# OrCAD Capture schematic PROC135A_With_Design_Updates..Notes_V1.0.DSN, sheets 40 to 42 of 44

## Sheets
40 40. HDMI INTERFACE: size C; title: HDMI INTERFACE
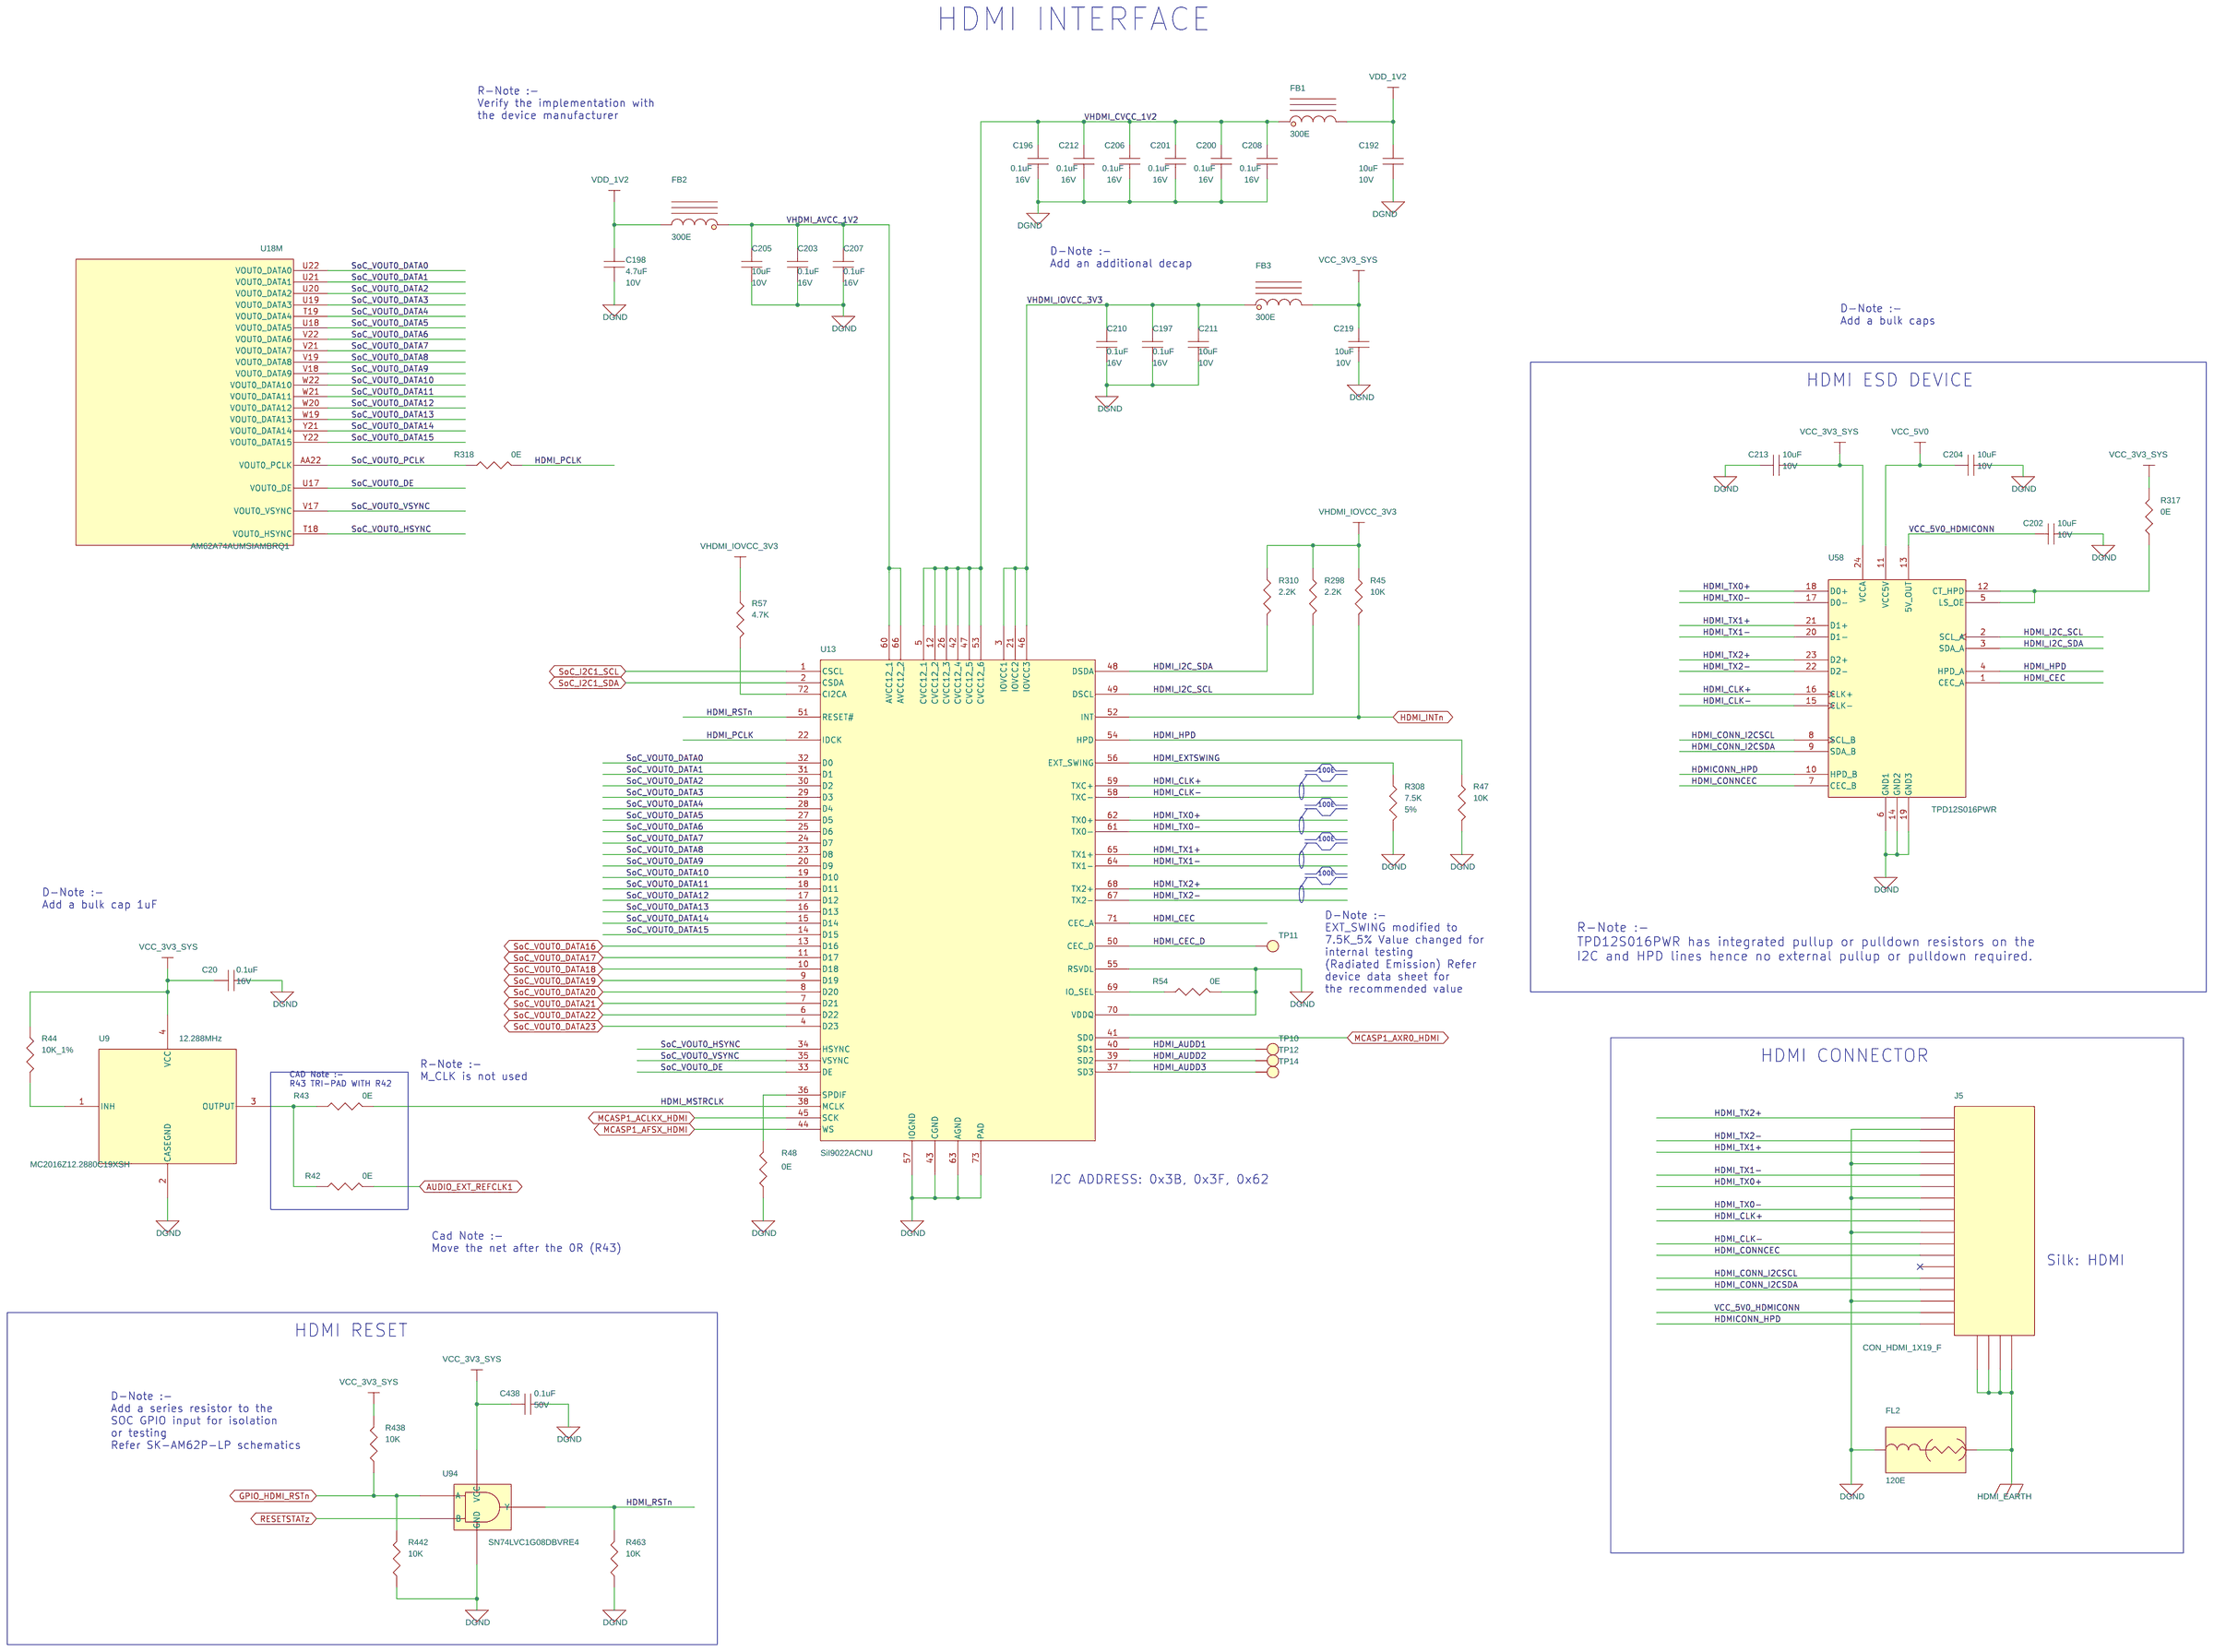
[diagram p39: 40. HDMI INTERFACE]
41 41. OSCILLATOR: size C; title: OSCILLATOR
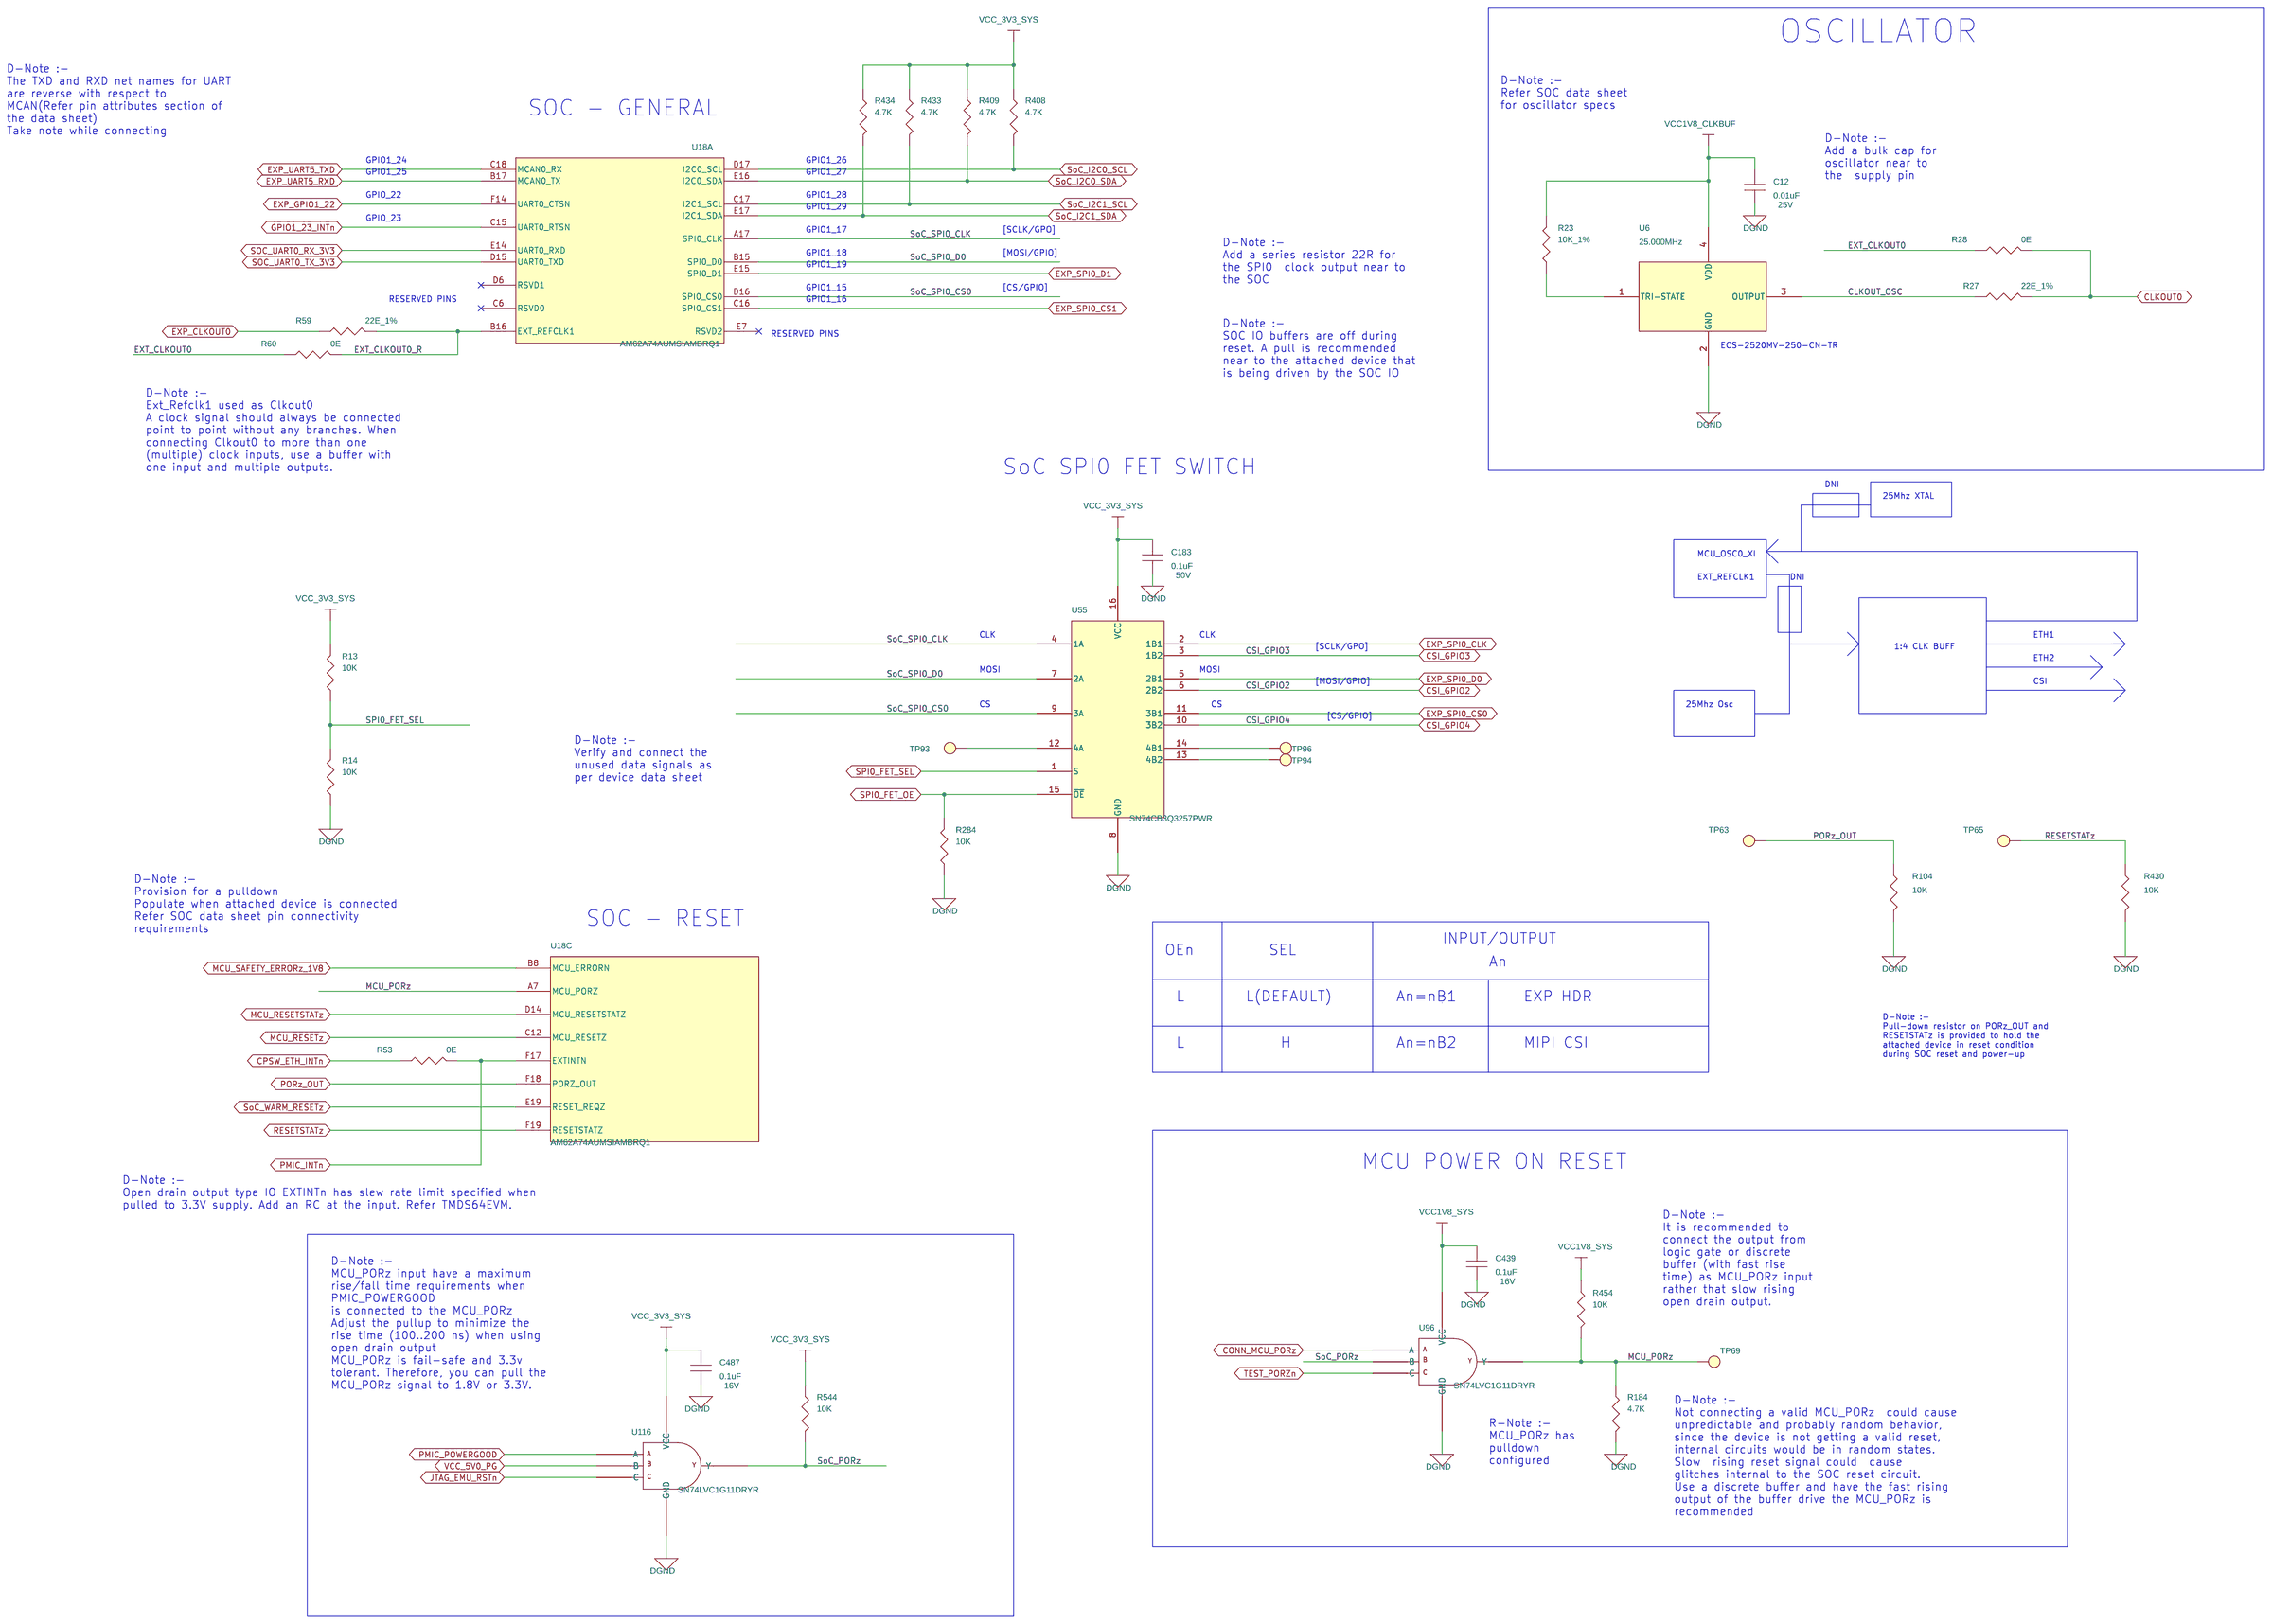
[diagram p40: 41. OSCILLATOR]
42 42. RESET: size C; title: RESET
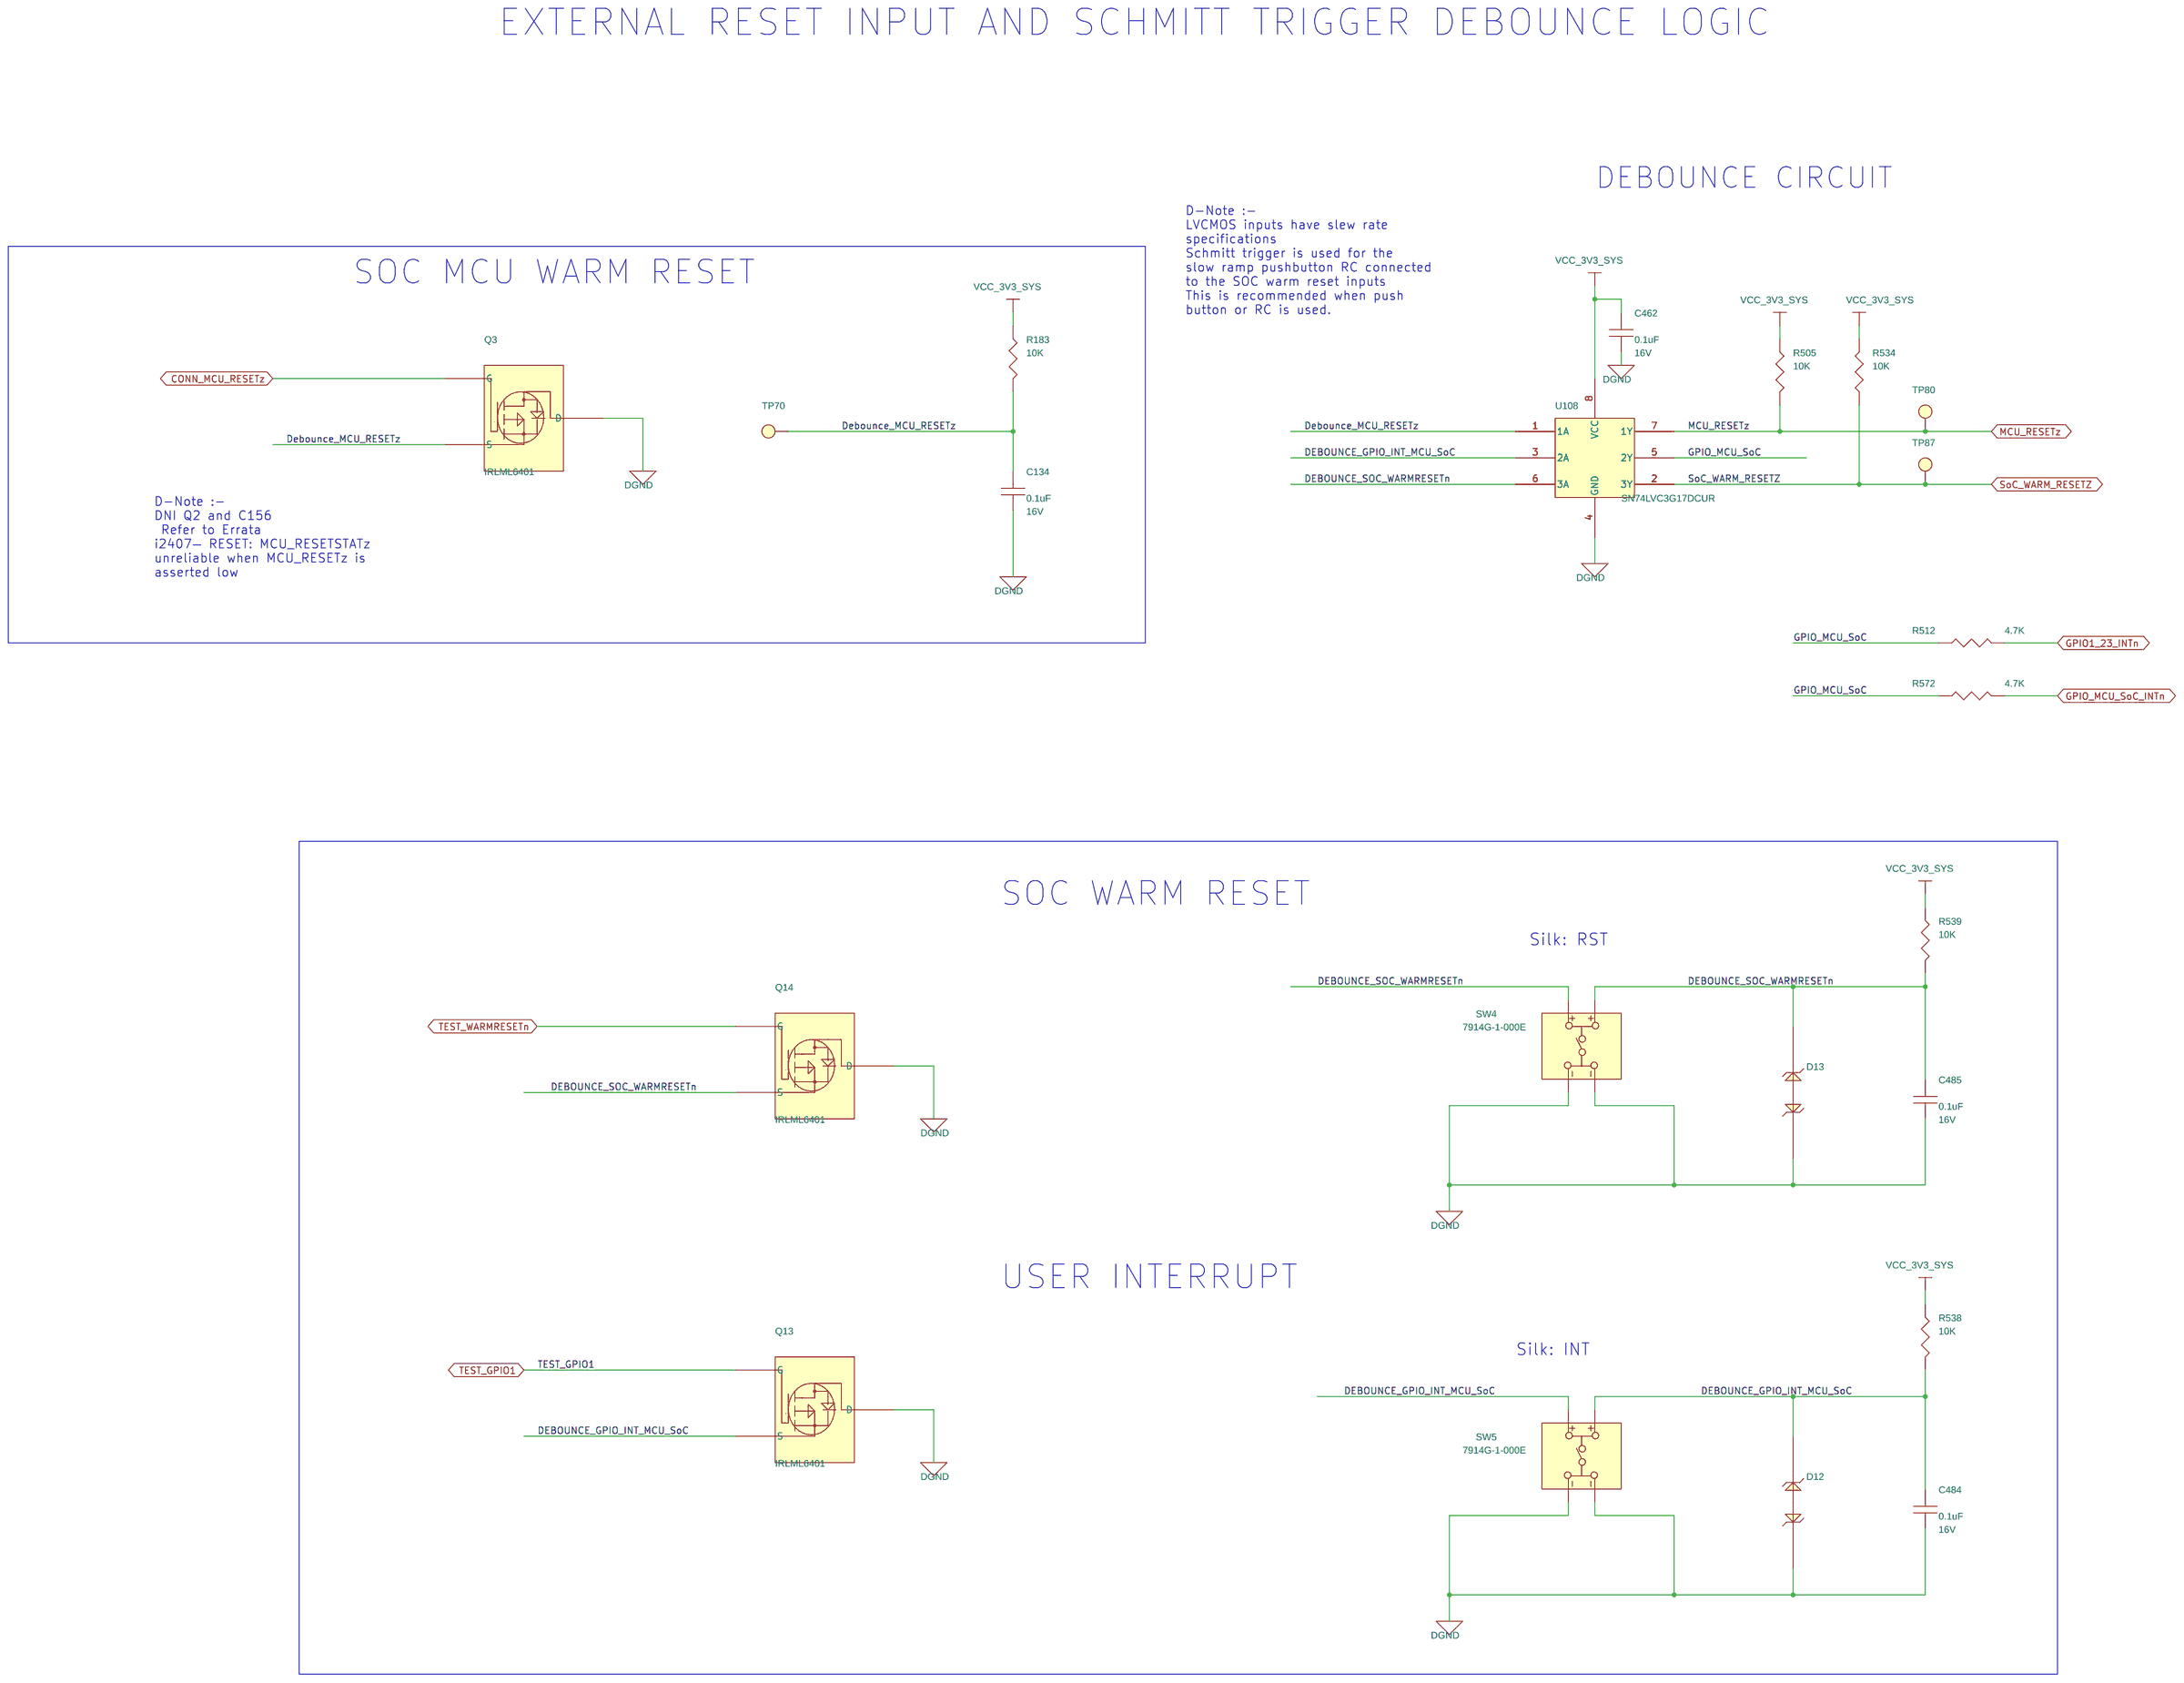
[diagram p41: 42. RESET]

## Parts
sheet 40. HDMI INTERFACE
C20  0.1uF  [CAP0201_0-5]
C192  10uF  [CAP0402_0-75]
C196  0.1uF  [CAP0201_0-5]
C197  0.1uF  [CAP0201_0-5]
C198  4.7uF  [CAP0402_0-75]
C200  0.1uF  [CAP0201_0-5]
C201  0.1uF  [CAP0201_0-5]
C202  10uF  [CAP0402_0-75]
C203  0.1uF  [CAP0201_0-5]
C204  10uF  [CAP0402_0-75]
C205  10uF  [CAP0402_0-75]
C206  0.1uF  [CAP0201_0-5]
C207  0.1uF  [CAP0201_0-5]
C208  0.1uF  [CAP0201_0-5]
C210  0.1uF  [CAP0201_0-5]
C211  10uF  [CAP0402_0-75]
C212  0.1uF  [CAP0201_0-5]
C213  10uF  [CAP0402_0-75]
C219  10uF  [CAP0402_0-75]
C438  0.1uF  [CAP0402_0-75]
FB1  300E  [IND0603]
FB2  300E  [IND0603]
FB3  300E  [IND0603]
FL2  120E  [EMIFIL_BLM15A_0402_0-6]
J5  CON_HDMI_1X19_F  [CON_19X1_10029449-001RLF_S_R_S_6-3]
R42  0E  [RES0201_0-5]
R43  0E  [RES0201_0-5]
R44  10K_1%  [RES0201_0-5]
R45  10K  [RES0201_0-5]
R47  10K  [RES0201_0-5]
R48  0E  [RES0201_0-5]
R54  0E  [RES0201_0-5]
R57  4.7K  [RES0201_0-5]
R298  2.2K  [RES0402_0-5]
R308  7.5K  [RES0402_0-5]
R310  2.2K  [RES0402_0-5]
R317  0E  [RES0201_0-5]
R318  0E  [RES0201_0-5]
R438  10K  [RES0201_0-5]
R442  10K  [RES0201_0-5]
R463  10K  [RES0201_0-5]
TP10  TP20_SMD  [TP20_SMD]
TP11  TP20_SMD  [TP20_SMD]
TP12  TP20_SMD  [TP20_SMD]
TP14  TP20_SMD  [TP20_SMD]
U9  12.288MHz  [OSC4_KC2016K_80X60_SMD_0-8]
U13  SiI9022ACNU  [QFN72_19-68_390X390_0-9]
U58  TPD12S016PWR  [TSSOP24_25-59_315X180_1-2]
U94  SN74LVC1G08DBVRE4  [SOT23-5]
sheet 41. OSCILLATOR
C12  0.01uF  [CAP0201_0-5]
C183  0.1uF  [CAP0402_0-75]
C439  0.1uF  [CAP0201_0-5]
C487  0.1uF  [CAP0201_0-5]
R13  10K  [RES0201_0-5]
R14  10K  [RES0201_0-5]
R23  10K_1%  [RES0201_0-5]
R27  22E_1%  [RES0201_0-5]
R28  0E  [RES0201_0-5]
R53  0E  [RES0201_0-5]
R59  22E_1%  [RES0201_0-5]
R60  0E  [RES0201_0-5]
R104  10K  [RES0201_0-5]
R184  4.7K  [RES0201_0-5]
R284  10K  [RES0201_0-5]
R408  4.7K  [RES0201_0-5]
R409  4.7K  [RES0201_0-5]
R430  10K  [RES0201_0-5]
R433  4.7K  [RES0201_0-5]
R434  4.7K  [RES0201_0-5]
R454  10K  [RES0201_0-5]
R544  10K  [RES0201_0-5]
TP63  TP20_SMD  [TP20_SMD]
TP65  TP20_SMD  [TP20_SMD]
TP69  TP20_SMD  [TP20_SMD]
TP93  TP20_SMD  [TP20_SMD]
TP94  TP20_SMD  [TP20_SMD]
TP96  TP20_SMD  [TP20_SMD]
U6  25.000MHz  [OSC4_ECS-2520MV_100X80_SMD_0-9]
U18  AM62A74AUMSIAMBRQ1  [FBGA484_31-49_710X710_2-7]  (sections A,B,C,D,E,F,G,H,I,J,K,L,M,N,O,P,Q)
U55  SN74CB3Q3257PWR  [TSSOP16_25-59_205X180]
U96  SN74LVC1G11DRYR  [SON6_SN74LVC2G17_40X60_0-6]
U116  SN74LVC1G11DRYR  [SON6_SN74LVC2G17_40X60_0-6]
sheet 42. RESET
C134  0.1uF  [CAP0201_0-5]
C462  0.1uF  [CAP0201_0-5]
C484  0.1uF  [CAP0201_0-5]
C485  0.1uF  [CAP0201_0-5]
D12  TPD1E10B06DPYR  [DIO_DFN0402_0-5]
D13  TPD1E10B06DPYR  [DIO_DFN0402_0-5]
Q3  IRLML6401  [TO_SOT23-123]
Q13  IRLML6401  [TO_SOT23-123]
Q14  IRLML6401  [TO_SOT23-123]
R183  10K  [RES0201_0-5]
R505  10K  [RES0201_0-5]
R512  4.7K  [RES0201_0-5]
R534  10K  [RES0201_0-5]
R538  10K  [RES0201_0-5]
R539  10K  [RES0201_0-5]
R572  4.7K  [RES0201_0-5]
SW4  7914G-1-000E  [SW4_100X216_200X200_SMD_4-2]
SW5  7914G-1-000E  [SW4_100X216_200X200_SMD_4-2]
TP70  TP20_SMD  [TP20_SMD]
TP80  TP20_SMD  [TP20_SMD]
TP87  TP20_SMD  [TP20_SMD]
U108  SN74LVC3G17DCUR  [VSSOP8_19-68_85X95_0-9]

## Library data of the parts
C20 C134 C439 C462 C484 C485 C487 = CAP: CAP CERAMIC 0.1uF 16V 10% X5R 0201; Alt_Mfr_name: YAGEO AMERICA; Alt_Mfr_part_number: CC0402KRX5R8BB104; Chkd/date: MANIRAJA/230118; Crtd /date: MANIRAJA/230118; Custom_Duty: 15%; Customs_HS_Code: 85322990; Distributor_name: DIGIKEY; Distributor_part_number: 490-14305-1-ND; Footprint Path: Y:\MIS_DATABASE\Library\ALTIUM_TOOL\PCB_FOOTPRINTS\Altium_Footprint_Lib.PcbLib; Height: 0.33MM; Library Path: Y:\MIS_DATABASE\Library\ALTIUM_TOOL\SCHEMATICS_PARTS\MS_DISCRETE_Library.schlib; Mfr_name: MURATA; Mfr_part_number: GRM033R61C104KE14D; Mistral Part No: 120009030072-R; Package: 0201; Part_type: CAPACITORS\CERAMIC; Project: TI_MAXIE_CPB; RoHS: RoHS; Temperature: -55°C+85°C; Tolerance: 10%; Voltage: 16V; Wattage: NA; Weight: 0.33mg; Datasheet: Y:\MIS_DATABASE\DATASHEETS\CAPACITORS\GRM033R61C104KE14.PDF
C192 C202 C204 C205 C211 C213 C219 = CAP: CAP CERAMIC 10uF 10V 20% X5R 0402; Chkd/date: MANIRAJA/300520; Crtd /date: ALVY/260520; Custom_Duty: 15%; Customs_HS_Code: 85322990; Distributor_name: DIGIKEY; Distributor_part_number: 490-GRM155R61A106ME11DTR-ND; Footprint Path: Y:\MIS_DATABASE\Library\ALTIUM_TOOL\PCB_FOOTPRINTS\Altium_Footprint_Lib.PcbLib; Height: 0.55MM; Library Path: Y:\MIS_DATABASE\Library\ALTIUM_TOOL\SCHEMATICS_PARTS\MS_DISCRETE_Library.schlib; Mfr_name: MURATA; Mfr_part_number: GRM155R61A106ME11D; Mistral Part No: 120013110019-R; Package: 0402; Part_type: CAPACITORS\CERAMIC; Project: QCS610_NANOSOM; RoHS: RoHS; Temperature: -55°C+85°C; Tolerance: 20%; Voltage: 10V; Wattage: NA; Weight: 3.1mg; Datasheet: Y:\MIS_DATABASE\DATASHEETS\CAPACITORS\MURATA-GXX-SER_NOV17.PDF
C196 C197 C200 C201 C203 C206-C208 C210 C212 = CAP: CAP CERAMIC 0.1uF 16V 10% X5R 0201; Chkd/date: MANIRAJA/230118; Crtd /date: MANIRAJA/230118; Custom_Duty: 15%; Customs_HS_Code: 85322990; Distributor_name: DIGIKEY; Distributor_part_number: 490-14305-1-ND; Footprint Path: Y:\MIS_DATABASE\Library\ALTIUM_TOOL\PCB_FOOTPRINTS\Altium_Footprint_Lib.PcbLib; Height: 0.33MM; Library Path: Y:\MIS_DATABASE\Library\ALTIUM_TOOL\SCHEMATICS_PARTS\MS_DISCRETE_Library.schlib; Mfr_name: MURATA; Mfr_part_number: GRM033R61C104KE14D; Mistral Part No: 120009030072-R; Package: 0201; Part_type: CAPACITORS\CERAMIC; Project: TI_MAXIE_CPB; RoHS: RoHS; Temperature: -55°C+85°C; Tolerance: 10%; Voltage: 16V; Wattage: NA; Weight: 0.33mg; Datasheet: Y:\MIS_DATABASE\DATASHEETS\CAPACITORS\GRM033R61C104KE14.PDF
C198 = CAP: CAP CERAMIC 4.7uF 10V 20% X5R 0402; Chkd/date: MANIRAJA/110718; Crtd /date: ALVY/110718; Custom_Duty: 15%; Customs_HS_Code: 85322990; Distributor_name: DIGIKEY; Distributor_part_number: 490-14306-1-ND; Footprint Path: Y:\MIS_DATABASE\Library\ALTIUM_TOOL\PCB_FOOTPRINTS\Altium_Footprint_Lib.PcbLib; Height: 0.65MM; Library Path: Y:\MIS_DATABASE\Library\ALTIUM_TOOL\SCHEMATICS_PARTS\MS_DISCRETE_Library.schlib; Mfr_name: MURATA; Mfr_part_number: GRM155R61A475MEAAD; Mistral Part No: 120012060002-R; Package: 0402; Part_type: CAPACITORS\CERAMIC; Project: TI_J7SVB_PCIE_ADD-ON-CARD; RoHS: RoHS; Temperature: -55°C+85°C; Tolerance: 20%; Voltage: 10V; Wattage: NA; Weight: 14mg; Datasheet: Y:\MIS_DATABASE\DATASHEETS\CAPACITORS\GRM155R61A475MEAAD.PDF
C183 C438 = CAP: CAP CERAMIC 0.1uF 50V 10% X7R 0402; Alt_Mfr_name: YAGEO AMERICA; Alt_Mfr_part_number: CC0402KRX5R8BB104; Chkd/date: MANIRAJA/261020; Crtd /date: ALVY/211020; Custom_Duty: 15%; Customs_HS_Code: 85322990; Distributor_name: DIGIKEY; Distributor_part_number: 490-10700-1-ND; Footprint Path: Y:\MIS_DATABASE\Library\ALTIUM_TOOL\PCB_FOOTPRINTS\Altium_Footprint_Lib.PcbLib; Height: 0.55MM; Library Path: Y:\MIS_DATABASE\Library\ALTIUM_TOOL\SCHEMATICS_PARTS\MS_DISCRETE_Library.schlib; Mfr_name: MURATA; Mfr_part_number: GRM155R71H104KE14D; Mistral Part No: 120011100014-R; Package: 0402; Part_type: CAPACITORS\CERAMIC; Project: J7_CP; RoHS: RoHS; Temperature: -55°C+125°C; Tolerance: 10%; Voltage: 50V; Wattage: NA; Weight: 3.1mg; Datasheet: Y:\MIS_DATABASE\DATASHEETS\CAPACITORS\GRM155R71H104KE14.PDF
FB1-FB3 = INDUCTOR_FERRITE: IND FERRITE CHIP 300E 500mA 0603; Alternate_mfr_name_A: TDK CORPORATION; Alternate_mfr_part_number_A: MMZ1608R301ATA00; Chkd/date: VASANTHA/190614; Crtd /date: NAVEED/160614; Custom_Duty: 24%; Customs_HS_Code: 85437099; Distributor_name: DIGIKEY; Distributor_name_A: DIGIKEY; Distributor_part_number: 445-2171-1-ND; Distributor_part_number_A: 445-2171-1-ND; Height: 0.75MM; Mfr_name: TDK CORPORATION; Mfr_part_number: MMZ1608R301A; Mistral Part No: 130014060028-R; Package: 0603; Part_type: INDUCTOR; Project: AEGIS_POM; RoHS: RoHS; Temperature: -55°C+125°C; Tolerance: NA; Voltage: NA; Wattage: NA; Weight: NA; Datasheet: Y:\MIS_DATABASE\DATASHEETS\DISCRETES\INDUCTORS\MMZSER.PDF
FL2 = EMIFILTER_IND: IND FERRITE BEAD CHIP 120E 2A 0402; Chkd/date: NAVEED/241114; Crtd /date: USMAN/170613; Custom_Duty: 24%; Customs_HS_Code: 85369090; Distributor_name: DIGIKEY; Distributor_part_number: 490-9656-1-ND; Footprint Path: Y:\MIS_DATABASE\Library\ALTIUM_TOOL\PCB_FOOTPRINTS\Altium_Footprint_Lib.PcbLib; Height: 0.55MM; Library Path: Y:\MIS_DATABASE\Library\ALTIUM_TOOL\SCHEMATICS_PARTS\MS_FILTER_Library.schlib; Mfr_name: MURATA; Mfr_part_number: BLM15PX121SN1D; Mistral Part No: 130013060022-R; Package: 0402; Part_type: INDUCTOR; Project: GEN_3-8; RoHS: RoHS; Temperature: -55°C+125°C; Tolerance: 25%; Voltage: NA; Wattage: NA; Weight: 1mg; Datasheet: Y:\MIS_DATABASE\DATASHEETS\DISCRETES\INDUCTORS\BLM15-SN1-SER.PDF
J5 = CON_HDMI_19X1: CON HDMI-A TYPE 1X19 0.50MM PITCH FEMALE RT SMD; Chkd/date: VASANTHA/060117; Crtd /date: MUDDU/060510; Custom_Duty: 24%; Customs_HS_Code: 85369090; Distributor_name: DIGIKEY; Distributor_part_number: 609-1010-1-ND; Footprint Path: Y:\MIS_DATABASE\Library\ALTIUM_TOOL\PCB_FOOTPRINTS\Altium_Footprint_Lib.PcbLib; Height: 6.30MM; Library Path: Y:\MIS_DATABASE\Library\ALTIUM_TOOL\SCHEMATICS_PARTS\MS_CONNECTOR_Library.schlib; Mfr_name: FCI; Mfr_part_number: 10029449-001RLF; Mistral Part No: 150010050001-R; Package: SMD; Part_type: CONNECTOR\HDMI; Project: SHIVA; RoHS: RoHS; Temperature: -20°C+85°C; Tolerance: NA; Voltage: NA; Wattage: NA; Weight: 2700mg; Datasheet: Y:\MIS_DATABASE\DATASHEETS\CONNECTORS\10029449-001RLF.PDF
R28 R42 R43 R48 R53 R54 R60 R317 = RESISTOR: RES 0E 1/20W 5% 0201; Chkd/date: NAVEED/301214; Crtd /date: MUDDU/120710; Custom_Duty: 15%; Customs_HS_Code: 85332119; Distributor_name: DIGIKEY; Distributor_part_number: 311-0.0NCT-ND; Footprint Path: Y:\MIS_DATABASE\Library\ALTIUM_TOOL\PCB_FOOTPRINTS\Altium_Footprint_Lib.PcbLib; Height: 0.26MM; Library Path: Y:\MIS_DATABASE\Library\ALTIUM_TOOL\SCHEMATICS_PARTS\MS_DISCRETE_Library.schlib; Mfr_name: YAGEO AMERICA; Mfr_part_number: RC0201JR-070RL; Mistral Part No: 110010070067-R; Package: 0201; Part_type: RESISTORS\FIXED; Project: PB_BUGBASE; RoHS: RoHS; Temperature: -55°C+125°C; Tolerance: 5%; Voltage: NA; Wattage: 1/20W; Weight: 0.17mg; Datasheet: Y:\MIS_DATABASE\DATASHEETS\RESISTORS\RCXXXXL-SER_MAR18.PDF
R23 R44 = RESISTOR: RES 10K 1/20W 1% 0201; Chkd/date: VASANTHA/270117; Crtd /date: MANIRAJA/270117; Custom_Duty: 15%; Customs_HS_Code: 85332119; Distributor_name: DIGIKEY; Distributor_part_number: 311-10.0KMCT-ND; Footprint Path: Y:\MIS_DATABASE\Library\ALTIUM_TOOL\PCB_FOOTPRINTS\Altium_Footprint_Lib.PcbLib; Height: 0.26MM; Library Path: Y:\MIS_DATABASE\Library\ALTIUM_TOOL\SCHEMATICS_PARTS\MS_DISCRETE_Library.schlib; Mfr_name: YAGEO AMERICA; Mfr_part_number: RC0201FR-0710KL; Mistral Part No: 110011040018-R; Package: 0201; Part_type: RESISTORS\FIXED; Project: GOLDEN-I LITE; RoHS: RoHS; Temperature: -55°C+125°C; Tolerance: 1%; Voltage: NA; Wattage: 1/20W; Weight: 0.17mg; Datasheet: Y:\MIS_DATABASE\DATASHEETS\RESISTORS\RCXXXXL-SER_MAR18.PDF
R13 R14 R45 R47 R104 R183 R284 R430 R438 R442 R454 R463 R505 R534 R538 R539 R544 = RESISTOR: RES 10K 1/20W 5% 0201; Chkd/date: MANIRAJA/050517; Crtd /date: MANIRAJA/050517; Custom_Duty: 15%; Customs_HS_Code: 85332119; Distributor_name: DIGIKEY; Distributor_part_number: 311-10KNCT-ND; Footprint Path: Y:\MIS_DATABASE\Library\ALTIUM_TOOL\PCB_FOOTPRINTS\Altium_Footprint_Lib.PcbLib; Height: 0.26MM; Library Path: Y:\MIS_DATABASE\Library\ALTIUM_TOOL\SCHEMATICS_PARTS\MS_DISCRETE_Library.schlib; Mfr_name: YAGEO AMERICA; Mfr_part_number: RC0201JR-0710KL; Mistral Part No: 110010070051-R; Package: 0201; Part_type: RESISTORS\FIXED; Project: GOLDEN-I LITE; RoHS: RoHS; Temperature: -55°C+125°C; Tolerance: 5%; Voltage: NA; Wattage: 1/20W; Weight: 0.17mg; Datasheet: Y:\MIS_DATABASE\DATASHEETS\RESISTORS\RCXXXXL-SER_MAR18.PDF
R57 R184 R408 R409 R433 R434 = RESISTOR: RES 4.7K 1/20W 5% 0201; Chkd/date: MANIRAJA/200921; Crtd /date: ALVY/200921; Custom_Duty: 15%; Customs_HS_Code: 85332119; Distributor_name: DIGIKEY; Distributor_part_number: 311-4.7KNCT-ND; Footprint Path: Y:\MIS_DATABASE\Library\ALTIUM_TOOL\PCB_FOOTPRINTS\Altium_Footprint_Lib.PcbLib; Height: 0.26MM; Library Path: Y:\MIS_DATABASE\Library\ALTIUM_TOOL\SCHEMATICS_PARTS\MS_DISCRETE_Library.schlib; Mfr_name: YAGEO AMERICA; Mfr_part_number: RC0201JR-074K7L; Mistral Part No: 110021090007-R; Package: 0201; Part_type: RESISTORS\FIXED; Project: TI_AM62x SKEVM_BRD; RoHS: RoHS; Temperature: -55°C+125°C; Tolerance: 5%; Voltage: NA; Wattage: 1/20W; Weight: 0.17mg; Datasheet: Y:\MIS_DATABASE\DATASHEETS\RESISTORS\RCXXXXL-SER_MAR18.PDF
R298 R310 = RESISTOR: RES 2.2K 1/16W 5% 0402; Chkd/date: VASANTHA/061216; Crtd /date: BAVISH/021210; Custom_Duty: 15%; Customs_HS_Code: 85332119; Distributor_name: DIGIKEY; Distributor_part_number: 311-2.2KJRCT-ND; Footprint Path: Y:\MIS_DATABASE\Library\ALTIUM_TOOL\PCB_FOOTPRINTS\Altium_Footprint_Lib.PcbLib; Height: 0.40MM; Library Path: Y:\MIS_DATABASE\Library\ALTIUM_TOOL\SCHEMATICS_PARTS\MS_DISCRETE_Library.schlib; Mfr_name: YAGEO AMERICA; Mfr_part_number: RC0402JR-072K2L; Mistral Part No: 110010120018-R; Package: 0402; Part_type: RESISTORS\FIXED; Project: TE4; RoHS: RoHS; Temperature: -55°C+155°C; Tolerance: 5%; Voltage: NA; Wattage: 1/16W; Weight: 0.65mg; Datasheet: Y:\MIS_DATABASE\DATASHEETS\RESISTORS\RCXXXXL-SER_MAR18.PDF
R308 = RESISTOR: RES 7.5K 1/16W 5% 0402; Chkd/date: MAZHAR/280108; Crtd /date: USMAN/280108; Custom_Duty: 15%; Customs_HS_Code: 85332119; Distributor_name: DIGIKEY; Distributor_part_number: 541-7.5KJCT-ND; Footprint Path: Y:\MIS_DATABASE\Library\ALTIUM_TOOL\PCB_FOOTPRINTS\Altium_Footprint_Lib.PcbLib; Height: 0.40MM; Library Path: Y:\MIS_DATABASE\Library\ALTIUM_TOOL\SCHEMATICS_PARTS\MS_DISCRETE_Library.schlib; Mfr_name: VISHAY; Mfr_part_number: CRCW04027K50JNED; Mistral Part No: 110009031092-R; Package: 0402; Part_type: RESISTORS\FIXED; Project: TELEMETRY ENCODER; RoHS: RoHS; Temperature: -55°C+155°C; Tolerance: 5%; Voltage: NA; Wattage: 1/16W; Weight: 0.65mg; Datasheet: Y:\MIS_DATABASE\DATASHEETS\RESISTORS\CRCW0603.PDF
R318 = RESISTOR: RES 0E 1/20W 5% 0201; Chkd/date: NAVEED/301214; Crtd /date: MUDDU/120710; Custom_Duty: 15%; Customs_HS_Code: 85332119; Distributor_name: DIGIKEY; Distributor_part_number: 311-0.0NCT-ND; Footprint Path: Y:\MIS_DATABASE\Library\ALTIUM_TOOL\PCB_FOOTPRINTS\Altium_Footprint_Lib.PcbLib; Height: 0.26MM; Library Path: Y:\MIS_DATABASE\Library\ALTIUM_TOOL\SCHEMATICS_PARTS\MS_DISCRETE_Library.schlib; Mfr_name: YAGEO AMERICA; Mfr_part_number: RC0201JR-070RL; Mistral Part No: 110010070067-R; Package: 0201; Part_type: RESISTORS\FIXED; Project: PB_BUGBASE; RoHS: RoHS; SIGNAL_MODEL: RESISTOR_RES0201_0-5_0E_0E; Temperature: -55°C+125°C; Tolerance: 5%; Voltage: NA; Wattage: 1/20W; Weight: 0.17mg; Datasheet: Y:\MIS_DATABASE\DATASHEETS\RESISTORS\RCXXXXL-SER_MAR18.PDF
TP10-TP12 TP14 TP63 TP65 TP69 TP70 TP80 TP87 TP93 TP94 TP96 = TESTPOINT: TESTPOINT CIR 20 SMD; Chkd/date: SHREESHAIL/171006; Crtd /date: MAZHAR/171006; Custom_Duty: NA; Customs_HS_Code: NA; Distributor_name: NA; Distributor_part_number: NA; Footprint Path: Y:\MIS_DATABASE\Library\ALTIUM_TOOL\PCB_FOOTPRINTS\Altium_Footprint_Lib.PcbLib; Height: NA; Library Path: Y:\MIS_DATABASE\Library\ALTIUM_TOOL\SCHEMATICS_PARTS\MS_DISCRETE_Library.schlib; MECHANICAL 3D STEP FILE: NA; Mfr_name: LOCAL; Mistral Part No: NA; Package: SMD; Project: BT MODULE_CSRBC04; RoHS: NA; Temperature: NA; Tolerance: NA; Voltage: NA; Wattage: NA; Weight: NA; Datasheet: NA
U9 = OSC4_KC7050K: OSC 12.288MHz CMOS AUTO SMD; Chkd/date: ALVY/310521; Crtd /date: TAMILARASU/310522; Custom_Duty: 24%; Customs_HS_Code: 85437099; Distributor_name: DIGIKEY; Distributor_part_number: 478-MC2016Z12.2880C19XSHCT-ND; Footprint Path: Y:\MIS_DATABASE\Library\ALTIUM_TOOL\PCB_FOOTPRINTS\Altium_Footprint_Lib.PcbLib; Height: 0.80MM; Library Path: Y:\MIS_DATABASE\Library\ALTIUM_TOOL\SCHEMATICS_PARTS\MS_DISCRETE_Library.schlib; Mfr_name: KYOCERA; Mfr_part_number: MC2016Z12.2880C19XSH; Mistral Part No: 130022050049-R; Package: SMD; Part_type: OSCILLATORS; Project: TI_AM62A_SK_EVM; RoHS: RoHS; Temperature: -40°C+125°C; Tolerance: NA; Voltage: NA; Wattage: NA; Weight: NA; Datasheet: Y:\MIS_DATABASE\DATASHEETS\MISC\CRY_OSC\MC-Z-SER.PDF
U13 = SII9022ACNU_QFN72: IC HDMI TRANSMITTER QFN72; Chkd/date: MANIRAJA/270818; Crtd /date: MUDDU/310510; Custom_Duty: 15%; Customs_HS_Code: 85423100; Distributor_name: NA; Distributor_part_number: NA; Footprint Path: Y:\MIS_DATABASE\Library\ALTIUM_TOOL\PCB_FOOTPRINTS\Altium_Footprint_Lib.PcbLib; Height: 0.90MM; Library Path: Y:\MIS_DATABASE\Library\ALTIUM_TOOL\SCHEMATICS_PARTS\MS_COMBINATIONAL_Library.schlib; Library Ref: SiI9022ACNU_QFN72; Mfr_name: SILICON IMAGE; Mistral Part No: 141010060001; Package: QFN72; Part_type: ICS\DIGITAL\PERIPHERAL; Project: CENTAURUS; RoHS: NA; Temperature: -20°C+85°C; Tolerance: NA; Voltage: NA; Wattage: NA; Weight: NA; Datasheet: Y:\MIS_DATABASE\DATASHEETS\ICS\DIGITAL\PERIPHERAL\SiI9022.PDF
U58 = TPD12S016PW_TSSOP24: IC HDMI COMPANION CHIP WITH I2C LEVEL SHIFTING,12-CH ESD TSSOP24; Chkd/date: MANIRAJA/110917; Crtd /date: BAVISH/180811; Custom_Duty: 15%; Customs_HS_Code: 85423100; Distributor_name: DIGIKEY; Distributor_part_number: 296-29690-1-ND; Height: 1.20MM; Mfr_name: TEXAS INSTRUMENTS; Mistral Part No: 141011080021-R; Package: TSSOP24; Part_type: ICS\INTERFACE; Project: DM385EVM_BASE-BOARD; RoHS: RoHS; Temperature: -40°C+85°C; Tolerance: NA; Voltage: NA; Wattage: NA; Weight: 212mg; Datasheet: Y:\MIS_DATABASE\DATASHEETS\ICS\INTERFACE\TPD12S016.PDF
U94 = SN74LVC1G08DBVRE4_SOT23-5: IC SINGLE 2-INPUT POSITIVE AND GATE SOT23-5; Chkd/date: SUHAS/221010; Crtd /date: USMAN/151008; Custom_Duty: 15%; Customs_HS_Code: 85423100; Distributor_name: DIGIKEY; Distributor_part_number: SN74LVC1G08DBVRE4-ND; Height: 1.45MM; Mfr_name: TEXAS INSTRUMENTS; Mistral Part No: 141009060026-R; Part_type: ICS\DIGITAL\GATES; Project: KHAN_MAIN; RoHS: Sb/ Br FREE; Temperature: -40°C+85°C; Datasheet: Y:\MIS_DATABASE\DATASHEETS\ICS\DIGITAL\GATES\SN74LVC1G08.PDF
C12 = CAP: CAP CERAMIC 0.01uF 25V 10% X5R 0201; Chkd/date: MANIRAJA/230118; Crtd /date: MANIRAJA/230118; Custom_Duty: 15%; Customs_HS_Code: 85322990; Distributor_name: DIGIKEY; Distributor_part_number: GRM033R61E103KA12J-ND; Footprint Path: Y:\MIS_DATABASE\Library\ALTIUM_TOOL\PCB_FOOTPRINTS\Altium_Footprint_Lib.PcbLib; Height: 0.33MM; Library Path: Y:\MIS_DATABASE\Library\ALTIUM_TOOL\SCHEMATICS_PARTS\MS_DISCRETE_Library.schlib; Mfr_name: MURATA; Mfr_part_number: GRM033R61E103KA12J; Mistral Part No: 120018010007-R; Package: 0201; Part_type: CAPACITORS\CERAMIC; Project: TI_MAXIE_CPB; RoHS: RoHS; Temperature: -55°C+85°C; Tolerance: 10%; Voltage: 25V; Wattage: NA; Weight: 0.33mg; Datasheet: Y:\MIS_DATABASE\DATASHEETS\CAPACITORS\GRM033R61E103KA12.PDF
R27 R59 = RESISTOR: RES 22E 1/20W 1% 0201; Chkd/date: MANIRAJA/080319; Crtd /date: ALVY/080319; Custom_Duty: 15%; Customs_HS_Code: 85332119; Distributor_name: DIGIKEY; Distributor_part_number: YAG2518CT-ND; Footprint Path: Y:\MIS_DATABASE\Library\ALTIUM_TOOL\PCB_FOOTPRINTS\Altium_Footprint_Lib.PcbLib; Height: 0.26MM; Library Path: Y:\MIS_DATABASE\Library\ALTIUM_TOOL\SCHEMATICS_PARTS\MS_DISCRETE_Library.schlib; Mfr_name: YAGEO AMERICA; Mfr_part_number: RC0201FR-0722RL; Mistral Part No: 110009030522-R; Package: 0201; Part_type: RESISTORS\FIXED; Project: AM654x_SOM; RoHS: RoHS; Temperature: -55°C+125°C; Tolerance: 1%; Voltage: NA; Wattage: 1/20W; Weight: 0.17mg; Datasheet: Y:\MIS_DATABASE\DATASHEETS\RESISTORS\RCXXXXL-SER_MAR18.PDF
U6 = OSC4_ASFL3: OSC 25.000MHz CMOS SMD; Chkd/date: MANIRAJA/181120; Crtd /date: ALVY/181120; Custom_Duty: 24%; Customs_HS_Code: 85437099; Distributor_name: DIGIKEY; Distributor_part_number: XC2752CT-ND; Footprint Path: Y:\MIS_DATABASE\Library\ALTIUM_TOOL\PCB_FOOTPRINTS\Altium_Footprint_Lib.PcbLib; Height: 0.90MM; Library Path: Y:\MIS_DATABASE\Library\ALTIUM_TOOL\SCHEMATICS_PARTS\MS_DISCRETE_Library.schlib; Mfr_name: ECS INC; Mfr_part_number: ECS-2520MV-250-CN-TR; Mistral Part No: 130020110041-R; Package: SMD; Part_type: OSCILLATORS; Project: AM64X_SKEVM; RoHS: RoHS; Temperature: -40°C+85°C; Tolerance: NA; Voltage: NA; Wattage: NA; Weight: 311mg; Datasheet: Y:\MIS_DATABASE\DATASHEETS\MISC\CRY_OSC\ECS-2520MV.PDF
U18 = AM62A-EVM_SOC_FCBGA484: IC AM62A SK EVM SoC MICROPROCESSOR FCBGA484; Chkd/date: PRADEEP/020823; Crtd /date: PRADEEP/020823; Custom_Duty: 15%; Customs_HS_Code: 85423100; Distributor_name: NA; Distributor_part_number: NA; Footprint Path: Y:\MIS_DATABASE\Library\ALTIUM_TOOL\PCB_FOOTPRINTS\Altium_Footprint_Lib.PcbLib; Height: 2.65MM; Library Ref: AM62A-EVM_SoC_FCBGA484; Mfr_name: TEXAS INSTRUMENTS; Mistral Part No: 141230080001-R; Package: FCBGA484; Part_type: ICS\DIGITAL\MICROPROCESSOR; Project: TI_AM62A_SK_EVM; RoHS: NA; Temperature: NA; Tolerance: NA; Voltage: NA; Wattage: NA; Weight: NA; Datasheet: Y:\MIS_DATABASE\DATASHEETS\ICS\DIGITAL\MICROCONTROLLER\AM62A_SK_EVM.PDF
U55 = SN74CB3Q3257PWR_TSSOP16: IC 4BIT 1-OF-2 FET MULTIPLEXER/DEMULTIPLEXER TSSOP16; Chkd/date: SUHAS/251010; Crtd /date: USMAN/060109; Custom_Duty: 15%; Customs_HS_Code: 85423100; Distributor_name: DIGIKEY; Distributor_part_number: 296-19138-1-ND; Height: 1.20MM; Mfr_name: TEXAS INSTRUMENTS; Mistral Part No: 141009030117-R; Package: TSSOP16; Part_type: ICS\DIGITAL\COMBINATIONAL; Project: OMAP_EVM; RoHS: Sb/ Br FREE; Temperature: -40°C+85°C; Datasheet: Y:\MIS_DATABASE\DATASHEETS\ICS\DIGITAL\COMBINATIONAL\SN74CB3Q3257.PDF
U96 U116 = SN74LVC1G11DCKR_SC70-6: IC SINGLE 3-INPUT POSITIVE-AND GATE SON6; Chkd/date: MANIRAJA/270121; Crtd /date: ALVY/270121; Custom_Duty: 15%; Customs_HS_Code: 85423100; Distributor_name: DIGIKEY; Distributor_part_number: 296-30120-1-ND; Footprint Path: Y:\MIS_DATABASE\Library\ALTIUM_TOOL\PCB_FOOTPRINTS\Altium_Footprint_Lib.PcbLib; Height: 0.60MM; Library Path: Y:\MIS_DATABASE\Library\ALTIUM_TOOL\SCHEMATICS_PARTS\MS_GATE_Library.schlib; Mfr_name: TEXAS INSTRUMENTS; Mistral Part No: 141021010013-R; Package: SON6; Part_type: ICS\DIGITAL\GATES; Project: AM64X_SKEVM; RoHS: RoHS; Temperature: -40°C+125°C; Tolerance: NA; Voltage: NA; Wattage: NA; Weight: 33mg; Datasheet: Y:\MIS_DATABASE\DATASHEETS\ICS\DIGITAL\GATES\SN74LVC1G_NOV16.PDF
D12 D13 = DIODE_SOD323: DIODE 1CH ESD PROTECTION X1SON2; Chkd/date: MANIRAJA/040420; Crtd /date: VASANTHA/181114; Custom_Duty: 15%; Customs_HS_Code: 85423100; Distributor_name: DIGIKEY; Distributor_part_number: 296-30406-1-ND; Footprint Path: Y:\MIS_DATABASE\Library\ALTIUM_TOOL\PCB_FOOTPRINTS\Altium_Footprint_Lib.PcbLib; Height: 0.45MM; Library Path: Y:\MIS_DATABASE\Library\ALTIUM_TOOL\SCHEMATICS_PARTS\MS_DISCRETE_Library.schlib; Mfr_name: TEXAS INSTRUMENTS; Mistral Part No: 130014110022-R; Package: X1SON2; Part_type: DIODE; Project: GALILEO_EVM; RoHS: RoHS; Temperature: -40°C+125°C; Tolerance: NA; Voltage: NA; Wattage: NA; Weight: 1mg; Datasheet: Y:\MIS_DATABASE\DATASHEETS\ICS\INTERFACE\TPD1E10B06-SER.PDF
Q3 Q13 Q14 = MOSFET_IRLML6401TR: TRANSISTOR MOSFET P-CHANNEL SOT23-3; Chkd/date: SHREESHAIL/020206; Crtd /date: MAZHAR/040505; Custom_Duty: 15%; Customs_HS_Code: 85412900; Distributor_name: DIGIKEY; Distributor_part_number: IRLML6401PBFCT-ND; Height: 1.11MM; Mfr_name: IRF; Mfr_part_number: IRLML6401TRPBF; Mistral Part No: 130009031213-P; Package: SOT23-3; Part_type: TRANSISTOR\MOSFET; Project: G4_SVGA; RoHS: Pb-Free; Temperature: -55°C+150°C; Tolerance: NA; Voltage: NA; Wattage: NA; Weight: NA; Datasheet: Y:\MIS_DATABASE\DATASHEETS\DISCRETES\TRANSISTORS_FETS\IRLML6401.PDF
R512 R572 = RESISTOR: RES 4.7K 1/20W 5% 0201; Chkd/date: MANIRAJA/200921; Crtd /date: ALVY/200921; Custom_Duty: 15%; Customs_HS_Code: 85332119; Distributor_name: DIGIKEY; Distributor_part_number: 311-4.7KNCT-ND; Footprint Path: Y:\MIS_DATABASE\Library\ALTIUM_TOOL\PCB_FOOTPRINTS\Altium_Footprint_Lib.PcbLib; Height: 0.26MM; Library Path: Y:\MIS_DATABASE\Library\ALTIUM_TOOL\SCHEMATICS_PARTS\MS_DISCRETE_Library.schlib; Manufacturer: YAGEO AMERICA; Mfr_name: YAGEO AMERICA; Mfr_part_number: RC0201JR-074K7L; Mistral Part No: 110021090007-R; Package: 0201; Part_type: RESISTORS\FIXED; Project: TI_AM62x SKEVM_BRD; RoHS: RoHS; Temperature: -55°C+125°C; Tolerance: 5%; Voltage: NA; Wattage: 1/20W; Weight: 0.17mg; Datasheet: Y:\MIS_DATABASE\DATASHEETS\RESISTORS\RCXXXXL-SER_MAR18.PDF
SW4 SW5 = 7914G-1-000E__7914G: SWITCH SPST-NO 4MM SQ SMD 7914G; Chkd/date: VASANTHA/271216; Crtd /date: BAVISH/051010; Custom_Duty: 24%; Customs_HS_Code: 85369090; Distributor_name: DIGIKEY; Distributor_part_number: 7914G-000ECT-ND; Height: 4.19MM; Library Ref: 7914G-1-000E _7914G; Mfr_name: BOURNS; Mistral Part No: 130015110004-R; Package: 7914G; Part_type: ELECTRO-MECHANICAL\SWITCH; Project: AAAUC; RoHS: RoHS; Temperature: -55°C+125°C; Tolerance: NA; Voltage: NA; Wattage: NA; Weight: NA; Datasheet: Y:\MIS_DATABASE\DATASHEETS\ICS\DIGITAL\COMBINATIONAL\7914G-1-000E.PDF
U108 = SN74LVC3G17DCUR_VSSOP8: IC TRIPLE SCHMITT-TRIGGER BUFFER VSSOP8; Chkd/date: MANIRAJA/280917; Crtd /date: MANIRAJA/280917; Custom_Duty: 15%; Customs_HS_Code: 85423100; Distributor_name: DIGIKEY; Distributor_part_number: 296-18818-1-ND; Height: 0.90MM; Mfr_name: TEXAS INSTRUMENTS; Mistral Part No: 141017090019-R; Package: VSSOP8; Part_type: ICS\DIGITAL\COMBINATIONAL; Project: TI_MAXIE_CPB; RoHS: RoHS; Temperature: -40°C+125°C; Tolerance: NA; Voltage: NA; Wattage: NA; Weight: 9.6mg; Datasheet: Y:\MIS_DATABASE\DATASHEETS\ICS\DIGITAL\COMBINATIONAL\SN74LVC3G17.PDF

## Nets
DGND: C12.1 C20.1 C134.1 C183.1 C192.2 C196.2 C197.2 C198.2 C200.2 C201.2 C202.2 C203.2 C204.2 C205.2 C206.2 C207.2 C208.2 C210.2 C211.2 C212.2 C213.1 C219.2 C438.2 C439.1 C462.1 C484.1 C485.1 C487.1 D12.1 D13.1 FL2.1 J5.2 J5.5 J5.8 J5.11 J5.17 Q3.3(D) Q13.3(D) Q14.3(D) R14.1 R47.2 R48.1 R54.2 R104.2 R184.2 R284.1 R308.2 R430.2 R442.1 R463.1 SW4.1 SW4.4 SW5.1 SW5.4 U6.2(GND) U9.2(CASEGND) U13.43(CGND) U13.55(RSVDL) U13.57(IOGND) U13.63(AGND) U13.70(VDDQ) U13.73(PAD) U55.8(GND) U58.6(GND1) U58.14(GND2) U58.19(GND3) U94.3(GND) U96.2(GND) U108.4(GND) U116.2(GND) ; also on sheet 9 10 11 12 13 14 15 16 17 18 19 20 21 22 23 24 25 26 27 28 29 30 31 32 33 34 35 36 37 38 39 43
VCC1V8_CLKBUF: C12.2 R23.2 U6.4(VDD) ; also on sheet 24
VCC1V8_SYS: C439.2 R454.1 U96.5(VCC) ; also on sheet 12 13 17 18 20 33 36 38 39
VCC_3V3_SYS: C20.2 C183.2 C213.2 C219.1 C438.1 C462.2 C487.2 FB3.2 R13.2 R44.2 R183.1 R317.2 R408.1 R409.1 R433.1 R434.1 R438.2 R505.1 R534.2 R538.1 R539.1 R544.1 U9.4(VCC) U55.16(VCC) U58.24(VCCA) U94.5(VCC) U108.8(VCC) U116.5(VCC) ; also on sheet 9 10 12 13 17 18 19 21 22 23 25 26 28 29 30 32 33 34 35 36 37 38 39
VCC_5V0: C204.1 U58.11(VCC5V) ; also on sheet 9 10 32 34 37
VCC_5V0_HDMICONN: C202.1 J5.18 U58.13(5V_OUT)
VCC_5V0_PG: U116.3(B) ; also on sheet 10
VDD_1V2: C192.1 C198.1 FB1.2 FB2.2 ; also on sheet 10
AUDIO_EXT_REFCLK1: R42.2 ; also on sheet 32
CLKOUT0: R27.2 R28.2 ; also on sheet 24
CLKOUT_OSC: R27.1 U6.3(OUTPUT)
CONN_MCU_PORz: U96.1(A) ; also on sheet 33
CONN_MCU_RESETz: Q3.1(G) ; also on sheet 33
CPSW_ETH_INTn: R53.1 ; also on sheet 22
CSI_GPIO2: U55.6(2B2) ; also on sheet 36
CSI_GPIO3: U55.3(1B2) ; also on sheet 36
CSI_GPIO4: U55.10(3B2) ; also on sheet 36
DEBOUNCE_GPIO_INT_MCU_SoC: C484.2 D12.2 Q13.2(S) R538.2 SW5.2 SW5.3 U108.3(2A)
Debounce_MCU_RESETz: C134.2 Q3.2(S) R183.2 TP70.1(TP) U108.1(1A)
DEBOUNCE_SOC_WARMRESETn: C485.2 D13.2 Q14.2(S) R539.2 SW4.2 SW4.3 U108.6(3A)
EXP_CLKOUT0: R59.1 ; also on sheet 32
EXP_GPIO1_22: U18.F14(UART0_CTSN) ; also on sheet 32
EXP_SPI0_CLK: U55.2(1B1) ; also on sheet 32
EXP_SPI0_CS0: U55.11(3B1) ; also on sheet 32
EXP_SPI0_CS1: U18.C16(SPI0_CS1) ; also on sheet 32
EXP_SPI0_D0: U55.5(2B1) ; also on sheet 32
EXP_SPI0_D1: U18.E15(SPI0_D1) ; also on sheet 32
EXP_UART5_RXD: U18.B17(MCAN0_TX) ; also on sheet 32
EXP_UART5_TXD: U18.C18(MCAN0_RX) ; also on sheet 32
EXT_CLKOUT0: R28.1 R60.1
EXT_CLKOUT0_R: R59.2 R60.2 U18.B16(EXT_REFCLK1)
GPIO1_23_INTn: R512.2 U18.C15(UART0_RTSN) ; also on sheet 39
GPIO_HDMI_RSTn: R438.1 R442.2 U94.1(A) ; also on sheet 39
GPIO_MCU_SoC: R512.1 R572.1 U108.5(2Y)
GPIO_MCU_SoC_INTn: R572.2 ; also on sheet 33
HDMI_AUDD1: TP10.1(TP) U13.40(SD1)
HDMI_AUDD2: TP12.1(TP) U13.39(SD2)
HDMI_AUDD3: TP14.1(TP) U13.37(SD3)
HDMI_CEC: U13.71(CEC_A) U58.1(CEC_A)
HDMI_CEC_D: TP11.1(TP) U13.50(CEC_D)
HDMI_CLK+: J5.10 U13.59(TXC+) U58.16(CLK+)
HDMI_CLK-: J5.12 U13.58(TXC-) U58.15(CLK-)
HDMI_CONN_I2CSCL: J5.15 U58.8(SCL_B)
HDMI_CONN_I2CSDA: J5.16 U58.9(SDA_B)
HDMI_CONNCEC: J5.13 U58.7(CEC_B)
HDMI_EARTH: FL2.2 J5.20 J5.21 J5.22 J5.23
HDMI_EXTSWING: R308.1 U13.56(EXT_SWING)
HDMI_HPD: R47.1 U13.54(HPD) U58.4(HPD_A)
HDMI_I2C_SCL: R298.2 U13.49(DSCL) U58.2(SCL_A)
HDMI_I2C_SDA: R310.2 U13.48(DSDA) U58.3(SDA_A)
HDMI_INTn: R45.2 U13.52(INT) ; also on sheet 39
HDMI_MSTRCLK: R43.2 U13.38(MCLK)
HDMI_PCLK: R318.2 U13.22(IDCK)
HDMI_RSTn: R463.2 U13.51(RESET#) U94.4(Y)
HDMI_TX0+: J5.7 U13.62(TX0+) U58.18(D0+)
HDMI_TX0-: J5.9 U13.61(TX0-) U58.17(D0-)
HDMI_TX1+: J5.4 U13.65(TX1+) U58.21(D1+)
HDMI_TX1-: J5.6 U13.64(TX1-) U58.20(D1-)
HDMI_TX2+: J5.1 U13.68(TX2+) U58.23(D2+)
HDMI_TX2-: J5.3 U13.67(TX2-) U58.22(D2-)
HDMICONN_HPD: J5.19 U58.10(HPD_B)
JTAG_EMU_RSTn: U116.6(C) ; also on sheet 29
MCASP1_ACLKX_HDMI: U13.45(SCK) ; also on sheet 39
MCASP1_AFSX_HDMI: U13.44(WS) ; also on sheet 39
MCASP1_AXR0_HDMI: U13.41(SD0) ; also on sheet 39
MCU_PORz: R184.1 R454.2 TP69.1(TP) U18.A7(MCU_PORZ) U96.4(Y)
MCU_RESETSTATz: U18.D14(MCU_RESETSTATZ) ; also on sheet 33
MCU_RESETz: R505.2 TP80.1(TP) U18.C12(MCU_RESETZ) U108.7(1Y)
MCU_SAFETY_ERRORz_1V8: U18.B8(MCU_ERRORN) ; also on sheet 33
PMIC_INTn: R53.2 U18.F17(EXTINTN) ; also on sheet 12
PMIC_POWERGOOD: U116.1(A) ; also on sheet 12
PORz_OUT: R104.1 TP63.1(TP) U18.F18(PORZ_OUT) ; also on sheet 19 22 23 26
RESETSTATz: R430.1 TP65.1(TP) U18.F19(RESETSTATZ) U94.2(B) ; also on sheet 18 19 20 22 23 26 37 38 39
SoC_I2C0_SCL: R408.2 U18.D17(I2C0_SCL) ; also on sheet 9 12 21 32
SoC_I2C0_SDA: R409.2 U18.E16(I2C0_SDA) ; also on sheet 9 12 21 32
SOC_I2C1_SCL: R433.2 U13.1(CSCL) U18.C17(I2C1_SCL) ; also on sheet 13 21 25 38 39
SOC_I2C1_SDA: R434.2 U13.2(CSDA) U18.E17(I2C1_SDA) ; also on sheet 13 21 25 38 39
SoC_PORz: R544.2 U96.3(B) U116.4(Y)
SoC_SPI0_CLK: U18.A17(SPI0_CLK) U55.4(1A)
SoC_SPI0_CS0: U18.D16(SPI0_CS0) U55.9(3A)
SoC_SPI0_D0: U18.B15(SPI0_D0) U55.7(2A)
SOC_UART0_RX_3V3: U18.E14(UART0_RXD) ; also on sheet 30
SOC_UART0_TX_3V3: U18.D15(UART0_TXD) ; also on sheet 30
SoC_VOUT0_DATA0: U13.32(D0) U18.U22(VOUT0_DATA0)
SoC_VOUT0_DATA1: U13.31(D1) U18.U21(VOUT0_DATA1)
SoC_VOUT0_DATA2: U13.30(D2) U18.U20(VOUT0_DATA2)
SoC_VOUT0_DATA3: U13.29(D3) U18.U19(VOUT0_DATA3)
SoC_VOUT0_DATA4: U13.28(D4) U18.T19(VOUT0_DATA4)
SoC_VOUT0_DATA5: U13.27(D5) U18.U18(VOUT0_DATA5)
SoC_VOUT0_DATA6: U13.25(D6) U18.V22(VOUT0_DATA6)
SoC_VOUT0_DATA7: U13.24(D7) U18.V21(VOUT0_DATA7)
SoC_VOUT0_DATA8: U13.23(D8) U18.V19(VOUT0_DATA8)
SoC_VOUT0_DATA9: U13.20(D9) U18.V18(VOUT0_DATA9)
SoC_VOUT0_DATA10: U13.19(D10) U18.W22(VOUT0_DATA10)
SoC_VOUT0_DATA11: U13.18(D11) U18.W21(VOUT0_DATA11)
SoC_VOUT0_DATA12: U13.17(D12) U18.W20(VOUT0_DATA12)
SoC_VOUT0_DATA13: U13.16(D13) U18.W19(VOUT0_DATA13)
SoC_VOUT0_DATA14: U13.15(D14) U18.Y21(VOUT0_DATA14)
SoC_VOUT0_DATA15: U13.14(D15) U18.Y22(VOUT0_DATA15)
SoC_VOUT0_DATA16: U13.13(D16) ; also on sheet 31
SoC_VOUT0_DATA17: U13.11(D17) ; also on sheet 31
SoC_VOUT0_DATA18: U13.10(D18) ; also on sheet 31
SoC_VOUT0_DATA19: U13.9(D19) ; also on sheet 31
SoC_VOUT0_DATA20: U13.8(D20) ; also on sheet 31
SoC_VOUT0_DATA21: U13.7(D21) ; also on sheet 31
SoC_VOUT0_DATA22: U13.6(D22) ; also on sheet 31
SoC_VOUT0_DATA23: U13.4(D23) ; also on sheet 31
SoC_VOUT0_DE: U13.33(DE) U18.U17(VOUT0_DE)
SoC_VOUT0_HSYNC: U13.34(HSYNC) U18.T18(VOUT0_HSYNC)
SoC_VOUT0_PCLK: R318.1 U18.AA22(VOUT0_PCLK)
SoC_VOUT0_VSYNC: U13.35(VSYNC) U18.V17(VOUT0_VSYNC)
SoC_WARM_RESETZ: R534.1 TP87.1(TP) U18.E19(RESET_REQZ) U108.2(3Y)
SPI0_FET_OE: R284.2 U55.15(~{OE}) ; also on sheet 39
SPI0_FET_SEL: R13.1 R14.2 U55.1(S) ; also on sheet 39
TEST_GPIO1: Q13.1(G) ; also on sheet 25 27
TEST_PORZn: U96.6(C) ; also on sheet 25 27
TEST_WARMRESETn: Q14.1(G) ; also on sheet 25 27
VHDMI_AVCC_1V2: C203.1 C205.1 C207.1 FB2.1 U13.60(AVCC12_1) U13.66(AVCC12_2)
VHDMI_CVCC_1V2: C196.1 C200.1 C201.1 C206.1 C208.1 C212.1 FB1.1 U13.5(CVCC12_1) U13.12(CVCC12_2) U13.26(CVCC12_3) U13.42(CVCC12_4) U13.47(CVCC12_5) U13.53(CVCC12_6)
VHDMI_IOVCC_3V3: C197.1 C210.1 C211.1 FB3.1 R45.1 R57.1 R298.1 R310.1 U13.3(IOVCC1) U13.21(IOVCC2) U13.46(IOVCC3)
N16927060: R57.2 U13.72(CI2CA)
N16927228: R54.1 U13.69(IO_SEL)
N16927289: R48.2 U13.36(SPDIF)
N16947096: R23.1 U6.1(TRI-STATE)
N17285208: R317.1 U58.5(LS_OE) U58.12(CT_HPD)
N19082749: R42.1 R43.1 U9.3(OUTPUT)
N23178675: TP96.1(TP) U55.14(4B1)
N23178691: TP94.1(TP) U55.13(4B2)
N23178707: TP93.1(TP) U55.12(4A)
N23413104: R44.1 U9.1(INH)

Not connected (* = marked no-connect by the designer): J5 14*; U18 C6(RSVD0)* D6(RSVD1)* E7(RSVD2)*

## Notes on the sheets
sheet 40
- HDMI INTERFACE
- R-Note :-
  Verify the implementation with
  the device manufacturer
- D-Note :-
  Add an additional decap
- D-Note :-
  Add a bulk caps
- HDMI ESD DEVICE
- 100E
- 100E
- 100E
- 100E
- D-Note :-
  Add a bulk cap 1uF
- D-Note :-
  EXT_SWING modified to
  7.5K_5% Value changed for
  internal testing
  (Radiated Emission) Refer
  device data sheet for
  the recommended value
- R-Note :-
  TPD12S016PWR has integrated pullup or pulldown resistors on the
  I2C and HPD lines hence no external pullup or pulldown required.
- HDMI CONNECTOR
- R-Note :-
  M_CLK is not used
- CAD Note :-
  R43 TRI-PAD WITH R42
- I2C ADDRESS: 0x3B, 0x3F, 0x62
- Cad Note :-
  Move the net after the 0R (R43)
- Silk: HDMI
- HDMI RESET
- D-Note :-
  Add a series resistor to the
  SOC GPIO input for isolation
  or testing
  Refer SK-AM62P-LP schematics
sheet 41
- OSCILLATOR
- D-Note :-
  The TXD and RXD net names for UART
  are reverse with respect to
  MCAN(Refer pin attributes section of
  the data sheet)
  Take note while connecting
- D-Note :-
  Refer SOC data sheet
  for oscillator specs
- SOC - GENERAL
- D-Note :-
  Add a bulk cap for
  oscillator near to
  the  supply pin
- GPIO1_24
- GPIO1_26
- GPIO1_25
- GPIO1_27
- GPIO_22
- GPIO1_28
- GPIO1_29
- GPIO_23
- GPIO1_17
- [SCLK/GPO]
- D-Note :-
  Add a series resistor 22R for
  the SPI0  clock output near to
  the SOC
- GPIO1_18
- [MOSI/GPIO]
- GPIO1_19
- GPIO1_15
- [CS/GPIO]
- RESERVED PINS
- GPIO1_16
- D-Note :-
  SOC IO buffers are off during
  reset. A pull is recommended
  near to the attached device that
  is being driven by the SOC IO
- RESERVED PINS
- ECS-2520MV-250-CN-TR
- D-Note :-
  Ext_Refclk1 used as Clkout0
  A clock signal should always be connected
  point to point without any branches. When
  connecting Clkout0 to more than one
  (multiple) clock inputs, use a buffer with
  one input and multiple outputs.
- SoC SPI0 FET SWITCH
- DNI
- 25Mhz XTAL
- MCU_OSC0_XI
- EXT_REFCLK1
- DNI
- CLK
- CLK
- ETH1
- [SCLK/GPO]
- 1:4 CLK BUFF
- ETH2
- MOSI
- MOSI
- [MOSI/GPIO]
- CSI
- CS
- CS
- 25Mhz Osc
- [CS/GPIO]
- D-Note :-
  Verify and connect the
  unused data signals as
  per device data sheet
- D-Note :-
  Provision for a pulldown
  Populate when attached device is connected
  Refer SOC data sheet pin connectivity
  requirements
- SOC - RESET
- INPUT/OUTPUT
- OEn
- SEL
- An
- L
- L(DEFAULT)
- An=nB1
- EXP HDR
- D-Note :-
  Pull-down resistor on PORz_OUT and
  RESETSTATz is provided to hold the
  attached device in reset condition
  during SOC reset and power-up
- L
- H
- An=nB2
- MIPI CSI
- MCU POWER ON RESET
- D-Note :-
  Open drain output type IO EXTINTn has slew rate limit specified when
  pulled to 3.3V supply. Add an RC at the input. Refer TMDS64EVM.
- D-Note :-
  It is recommended to
  connect the output from
  logic gate or discrete
  buffer (with fast rise
  time) as MCU_PORz input
  rather that slow rising
  open drain output.
- D-Note :-
  MCU_PORz input have a maximum
  rise/fall time requirements when
  PMIC_POWERGOOD
  is connected to the MCU_PORz
  Adjust the pullup to minimize the
  rise time (100..200 ns) when using
  open drain output
  MCU_PORz is fail-safe and 3.3v
  tolerant. Therefore, you can pull the
  MCU_PORz signal to 1.8V or 3.3V.
- D-Note :-
  Not connecting a valid MCU_PORz  could cause
  unpredictable and probably random behavior,
  since the device is not getting a valid reset,
  internal circuits would be in random states.
  Slow  rising reset signal could  cause
  glitches internal to the SOC reset circuit.
  Use a discrete buffer and have the fast rising
  output of the buffer drive the MCU_PORz is
  recommended
- R-Note :-
  MCU_PORz has
  pulldown
  configured
sheet 42
- EXTERNAL RESET INPUT AND SCHMITT TRIGGER DEBOUNCE LOGIC
- DEBOUNCE CIRCUIT
- D-Note :-
  LVCMOS inputs have slew rate
  specifications
  Schmitt trigger is used for the
  slow ramp pushbutton RC connected
  to the SOC warm reset inputs
  This is recommended when push
  button or RC is used.
- SOC MCU WARM RESET
- D-Note :-
  DNI Q2 and C156
   Refer to Errata
  i2407— RESET: MCU_RESETSTATz
  unreliable when MCU_RESETz is
  asserted low
- SOC WARM RESET
- Silk: RST
- USER INTERRUPT
- Silk: INT
